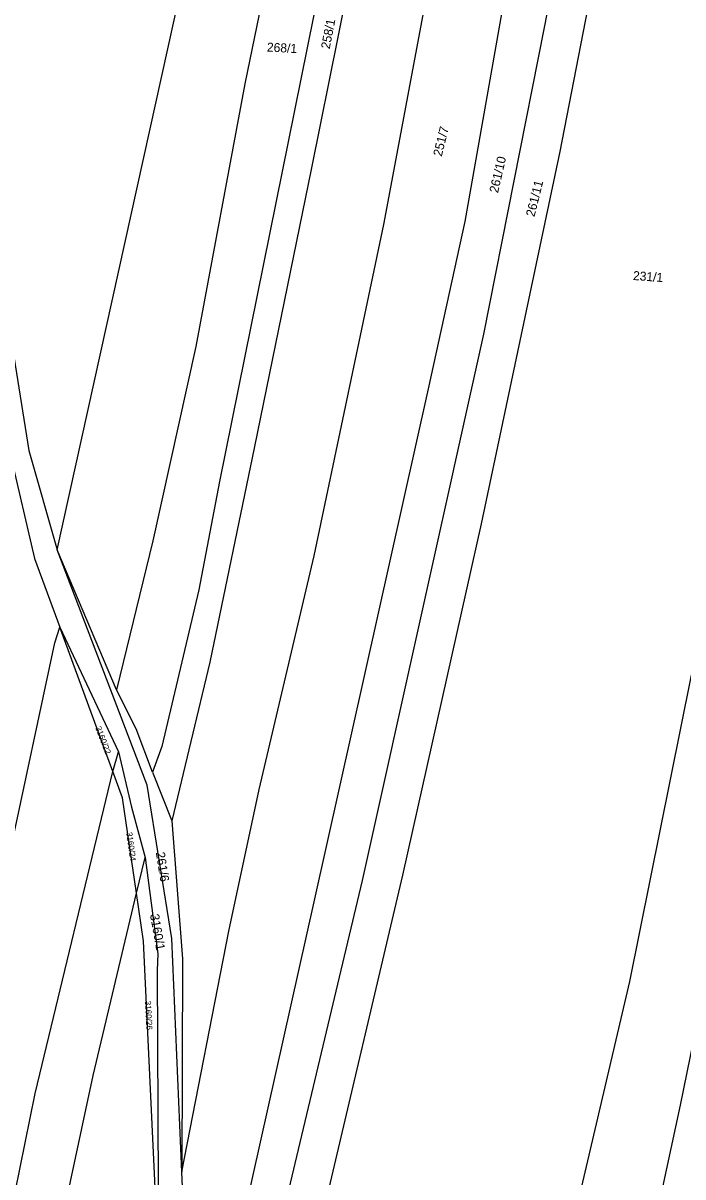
# Model space of a CAD drawing. Extents: x -776734 to -748832, y -1118122 to -976986.
# Drawn here: x -752966.3 to -752841.8, y -1114653.4 to -1114435.8 of the extents above; entities that cross this region are included whole.
import ezdxf

# ---------------------------------------------------------------- set-up
doc = ezdxf.new("R2010")
doc.units = 0
doc.layers.add('KM_Hranice parcel', color=7, linetype='Continuous')
doc.layers.add('KM_Parcelní čísla', color=7, linetype='Continuous')

msp = doc.modelspace()

# ---------------------------------------------------------------- linework, layer by layer
at = {"layer": 'KM_Hranice parcel'}
for p, q in [((-752948.69, -1114561.57), (-752959.91, -1114535.17)), ((-752959.4, -1114549.77), (-752948.34, -1114573.28)), ((-752949.38, -1114576.99), (-752959.4, -1114549.77)), ((-752949.38, -1114576.99), (-752948.34, -1114573.28)), ((-752941.94, -1114577.11), (-752938.26, -1114586.3)), ((-752944.93, -1114599.94), (-752943.32, -1114593.21)), ((-752934.12, -1114704.82), (-752936.38, -1114652.45))]:
    msp.add_line(p, q, dxfattribs=at)
for points in [[(-752872.21, -1114189.2), (-752889.69, -1114278.54), (-752899.59, -1114328.44), (-752912.33, -1114388.25), (-752924.51, -1114447.25), (-752933.76, -1114496.83), (-752941.89, -1114533.46), (-752948.69, -1114561.57)], [(-752861.64, -1114193.99), (-752866.97, -1114219.87), (-752883.88, -1114299.01), (-752895.48, -1114356.1), (-752911.52, -1114434.58), (-752929.25, -1114522.3), (-752933.21, -1114542.71), (-752940.19, -1114572.28), (-752941.94, -1114577.11)], [(-752856.36, -1114196.38), (-752861.91, -1114220.87), (-752871.2, -1114264.59), (-752878.44, -1114300.08), (-752884.83, -1114330.68), (-752901.96, -1114413.75), (-752911.95, -1114463.1), (-752922.74, -1114516.02), (-752931.12, -1114556.35), (-752938.26, -1114586.3)], [(-752936.38, -1114652.45), (-752927.54, -1114607.1), (-752921.77, -1114580.34), (-752911.41, -1114536.28), (-752898.3, -1114473.79), (-752890.49, -1114432.26), (-752883.47, -1114397), (-752872.32, -1114341.97), (-752864.19, -1114302.89), (-752852.12, -1114248.93), (-752842.24, -1114203)], [(-752934.12, -1114704.82), (-752928.8, -1114679.25), (-752911.41, -1114601.55), (-752889.83, -1114504.81), (-752882.93, -1114473.25), (-752875.16, -1114429.34), (-752857.99, -1114345.2), (-752852.05, -1114320.86), (-752840.08, -1114264.39), (-752828.31, -1114209.54)], [(-752929.9, -1114717.17), (-752924.26, -1114689.78), (-752902.28, -1114597.5), (-752879.37, -1114494.47), (-752867.97, -1114436.68), (-752857.5, -1114382.95), (-752852.15, -1114355.64), (-752836.88, -1114285.62), (-752821.72, -1114212.63)], [(-752814.9, -1114215.83), (-752823.67, -1114257.79), (-752828.11, -1114280.91), (-752845.29, -1114358.42), (-752865.07, -1114460.04), (-752879.89, -1114530.26), (-752894.73, -1114596.52), (-752909.92, -1114660.92), (-752922.77, -1114714.57), (-752925.81, -1114729.14)], [(-752877.51, -1114796.45), (-752864.37, -1114734.66), (-752855.23, -1114695.41), (-752848.48, -1114668.5), (-752842.28, -1114639.9), (-752832.25, -1114590.62), (-752814.67, -1114513.35), (-752808.19, -1114483.16), (-752800.05, -1114438.6), (-752784.13, -1114357.8), (-752769.94, -1114301.29), (-752757.23, -1114242.84)], [(-752784.53, -1114297.81), (-752790.74, -1114319.93), (-752803.68, -1114380.05), (-752814.75, -1114434.38), (-752827.59, -1114501.73), (-752840.34, -1114559.14), (-752851.92, -1114616.56), (-752864.77, -1114671.34), (-752878.1, -1114727), (-752891.1, -1114788.07)], [(-752959.91, -1114535.17), (-752936.61, -1114429.79), (-752913.12, -1114323.53)], [(-752973.26, -1114460.59), (-752968.55, -1114495.93), (-752965.24, -1114516.46), (-752959.91, -1114535.17)], [(-752973.28, -1114483.85), (-752972.18, -1114496.68), (-752968.79, -1114517.05), (-752964.17, -1114536.8), (-752959.4, -1114549.77)], [(-752936.38, -1114652.45), (-752938.28, -1114608.44), (-752942.9, -1114579.53), (-752959.91, -1114535.17)], [(-753035.22, -1114902.86), (-753030.76, -1114879.49), (-753016.74, -1114820.75), (-753007.19, -1114774.77), (-752985.34, -1114668.69), (-752977.68, -1114633.44), (-752960.36, -1114552.68), (-752959.4, -1114549.77)], [(-752941.94, -1114577.11), (-752944.99, -1114568.93), (-752948.69, -1114561.57)], [(-752948.34, -1114573.28), (-752945.9, -1114583.68), (-752943.32, -1114593.21)], [(-753020.14, -1114901.94), (-753015.82, -1114880.89), (-753004.67, -1114831.04), (-752992.55, -1114775.89), (-752973.57, -1114684.2), (-752964.06, -1114637.71), (-752949.38, -1114576.99)], [(-752944.93, -1114599.94), (-752947.56, -1114581.93), (-752949.38, -1114576.99)], [(-752938.26, -1114586.3), (-752936.29, -1114612.29), (-752936.38, -1114652.45)], [(-752943.32, -1114593.21), (-752940.9, -1114611.35), (-752941.04, -1114614.51), (-752940.8, -1114668.75)], [(-753009.89, -1114901.31), (-752994.51, -1114828.43), (-752983.39, -1114776.59), (-752968.12, -1114704.27), (-752953.14, -1114634.3), (-752944.93, -1114599.94)], [(-752940.8, -1114668.75), (-752943.6, -1114609), (-752944.93, -1114599.94)]]:
    msp.add_lwpolyline(points, dxfattribs=at)

# ---------------------------------------------------------------- texts
at = {"layer": 'KM_Parcelní čísla'}
for s, height, rotation, p in [('258/1', 1.7, 79, (-752908.495, -1114440.802)), ('268/1', 1.7, 357, (-752920.364, -1114441.178)), ('251/7', 1.7, 76, (-752887.355, -1114461.075)), ('261/10', 1.7, 77, (-752876.731, -1114467.961)), ('261/11', 1.7, 76, (-752869.845, -1114472.455)), ('231/1', 1.7, 356, (-752851.289, -1114484.267)), ('3160/22', 1.14, 290.999997, (-752952.746, -1114568.696)), ('3160/24', 1.14, 278, (-752946.883, -1114588.486)), ('261/6', 1.7, 279, (-752941.299, -1114592.262)), ('3160/1', 1.7, 280, (-752942.397, -1114603.977)), ('3160/26', 1.14, 273, (-752943.35, -1114620.231))]:
    msp.add_text(s, height=height, rotation=rotation, dxfattribs=at).set_placement(p)

doc.saveas('drawing.dxf')
